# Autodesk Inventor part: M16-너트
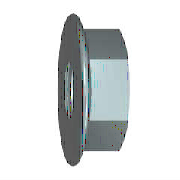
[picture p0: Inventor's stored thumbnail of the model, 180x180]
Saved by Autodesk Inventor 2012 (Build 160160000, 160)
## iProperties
IsCustomPart: 0
Company: 한국ATC센터
Created: 2009-02
Part Number: M16-너트
Material: Steel, Mild
Description: 플랜지붙이 6각 너트
Document SubType Name: Modeling
Standard: JIS B 1190
Designer: KYOUNG IL JANG
Standards Organization: JIS
Language: ko-KR
Size Designation: M 16
Categories: <MemberInstance><Categories><Category DisplayName="조임쇠" InternalName="e4da775c-781d-43d5-af7c-5136215cf5a6" Mnemonic="FSTN"><Category DisplayName="너트" InternalN
Density: 1 g/cm^3
Author: KYOUNG IL JANG
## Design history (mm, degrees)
body "Solid1"
workaxis "Work Axis1"
workplane "Work Plane1"
revolve "링" stored, may be unused: angle "d8" = 90 deg
sketch "스케치2"
  geometry: L1 (-11, -6.351)-(-11, 6.351); L2 (-11, 6.351)-(0, 12.702); L3 (0, 12.702)-(11, 6.351); L4 (11, 6.351)-(11, -6.351); L5 (11, -6.351)-(0, -12.702); L6 (0, -12.702)-(-11, -6.351); C1 r 4.9 at (0, 0); C2 r 14.7 at (0, 0) reference; 1 further point
  constraints: 12 end point, 1 centre point, 1 coincident, 1 vertical, 11 other
  dimensions: "d6" = 25.40341 distance of L5.end L2.end (= 1.1547 x SW)
extrude "본체" join sketch "스케치2" distance "d7" = 15 (= KOH); taper "d9" = 0 deg
revolve "모따기1" stored, may be unused: angle "d24" = 90 deg
sketch "스케치4"
  geometry: C1 r 14.7 at (0, 0) reference; 1 further point
  constraints: 1 coincident
hole "스레드" sketch "스케치4" diameter "d25" = 13.835; stored, may be unused: countersink angle "d29" = 82 deg, drill point angle "d31" = 118 deg; dims "d26" = 6, "d27" = 4, "d28" = 2, "d30" = 8
chamfer "모따기2" distance "d12" = 1.08253 (= -0.5 x GD1 + 0.5 x NND); stored, may be unused: angle "d13" = 30 deg, second distance "d46" = 1.08253 (= -0.5 x GD1 + 0.5 x NND)
chamfer "모따기3" distance "d51" = 1.08253 (= -0.5 x GD1 + 0.5 x NND); stored, may be unused: second distance "d52" = 2, angle "d53" = 45 deg
sketch "스케치1"
  geometry: L1 (-3.414, 0)-(18.069, 0) reference; L2 (6.015, 11)-(3.359, 15.6); L3 (6.015, 11)-(15, 11); L4 (15, 11)-(15, 0); L5 (6.015, 11)-(6.015, 0); L6 (0, -3.378)-(0, 20.266) reference; A1 r 1.8 centre (1.8, 14.7) between (3.359, 15.6) and (0, 14.7); 1 further point
  constraints: 8 end point, 3 point on line, 2 perpendicular, 2 point on circle, 2 tangent, 1 centre point, 1 parallel
  dimensions: "d2" = 22 diameter of L3 L1 (= SW); "d4" = 33 dimension on A1 L1 (= LADI); "d5" = 1.8 radius of A1 (= PHH); "d15" = 15 distance between parallel lines of L4 L6 (= KOH); "d16" = 30 deg angle of L6 L2 (= KEWI)
sketch "스케치3"
  geometry: L1 (5.032, 12.702)-(15, 12.702) reference; L2 (15, 6.351)-(15, 12.702) reference; L3 (0, -14.7)-(0, 14.7) reference; L4 (-3, 0)-(18, 0) reference; L5 (14.018, 12.702)-(15, 11)
  constraints: 2 end point, 2 point on line
  dimensions: "d10" = 30 deg angle of L2 L5 (= ANG1); "d11" = 22 diameter of L5.end L4 (= SW0)
other parameters: "ANG1" = 30 deg [user parameter; used in 1 equation term], "KEWI" = 30 deg [user parameter; used in 1 equation term], "NND" = 16 [user parameter; used in 3 equation terms], "LADI" = 33 [user parameter; used in 2 equation terms], "SW" = 22 [user parameter; used in 4 equation terms], "PHH" = 1.8 [user parameter; used in 2 equation terms], "KOH" = 15 [user parameter; used in 2 equation terms], "SW0" = 22 (= SW) [user parameter; used in 1 equation term], "GD1" = 13.83494 (computed from THREADDIA, PTC, TOA) [user parameter; used in 3 equation terms], "d1" = 33 (= LADI), "d3" = 1.8 (= PHH), "d45" = 0, "d47" = 0, "d49" = 0, "d54" = 0, "GUL" = 1.08253 (= 0.541266 x PTC) [user parameter], "TPU" = 5 (computed from PTC) [user parameter], "RR" = 2 [user parameter], "THREADDIA" = 16 [user parameter; used in 1 equation term], "TOA" = 30 deg [user parameter; used in 1 equation term], "PTC" = 2 [user parameter; used in 4 equation terms], "GAL" = 1.08253 (= 0.541266 x PTC) [user parameter], "E0" = 25.41 (= 1.155 x SW) [user parameter]
